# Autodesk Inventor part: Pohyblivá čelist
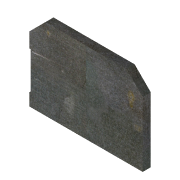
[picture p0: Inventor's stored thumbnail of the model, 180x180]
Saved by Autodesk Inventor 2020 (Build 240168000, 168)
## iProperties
Created: 2025-03
Part Number: Pohyblivá čelist
Material: Ocel
Document SubType Name: Modeling
Designer: doma
Density: 7.85 g/cm^3
Appearance: Plech
Mass: 1067.6 g
Surface Area: 317.657 cm^2
Volume: 136 cm^3
Author: doma
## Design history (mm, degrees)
sketch "Náčrt1"
  geometry: L1 (-70, -50)-(70, -50); L2 (70, -50)-(70, 50); L3 (70, 50)-(-70, 50); L4 (-70, 50)-(-70, -50); L5 (-70, -50)-(70, 50); L6 (70, -50)-(-70, 50); 1 further point
  constraints: 12 end point, 2 midpoint, 2 parallel, 1 horizontal, 1 perpendicular
  dimensions: "d0" = 140 distance of L3.end L2.end; "d1" = 100 distance of L2.end L1.end
extrude "Vysunutí1" new body sketch "Náčrt1" distance "d2" = 10; taper "d3" = 0 deg
chamfer "Zkosení1" distance "d4" = 20; stored, may be unused: second distance "d5" = 2, angle "d6" = 45 deg
chamfer "Zkosení2" distance "d7" = 3; stored, may be unused: second distance "d8" = 2, angle "d9" = 45 deg; dims "d10" = 18, "d11" = 47, "d12" = 15
node "Těleso1"
